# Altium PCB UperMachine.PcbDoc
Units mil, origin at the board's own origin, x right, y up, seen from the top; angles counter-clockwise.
Board outline 2283.46 x 2283.46 mil, 2 copper layers (Top Layer, Bottom Layer); 62 components, 71 nets, 256 pads, 137 vias.
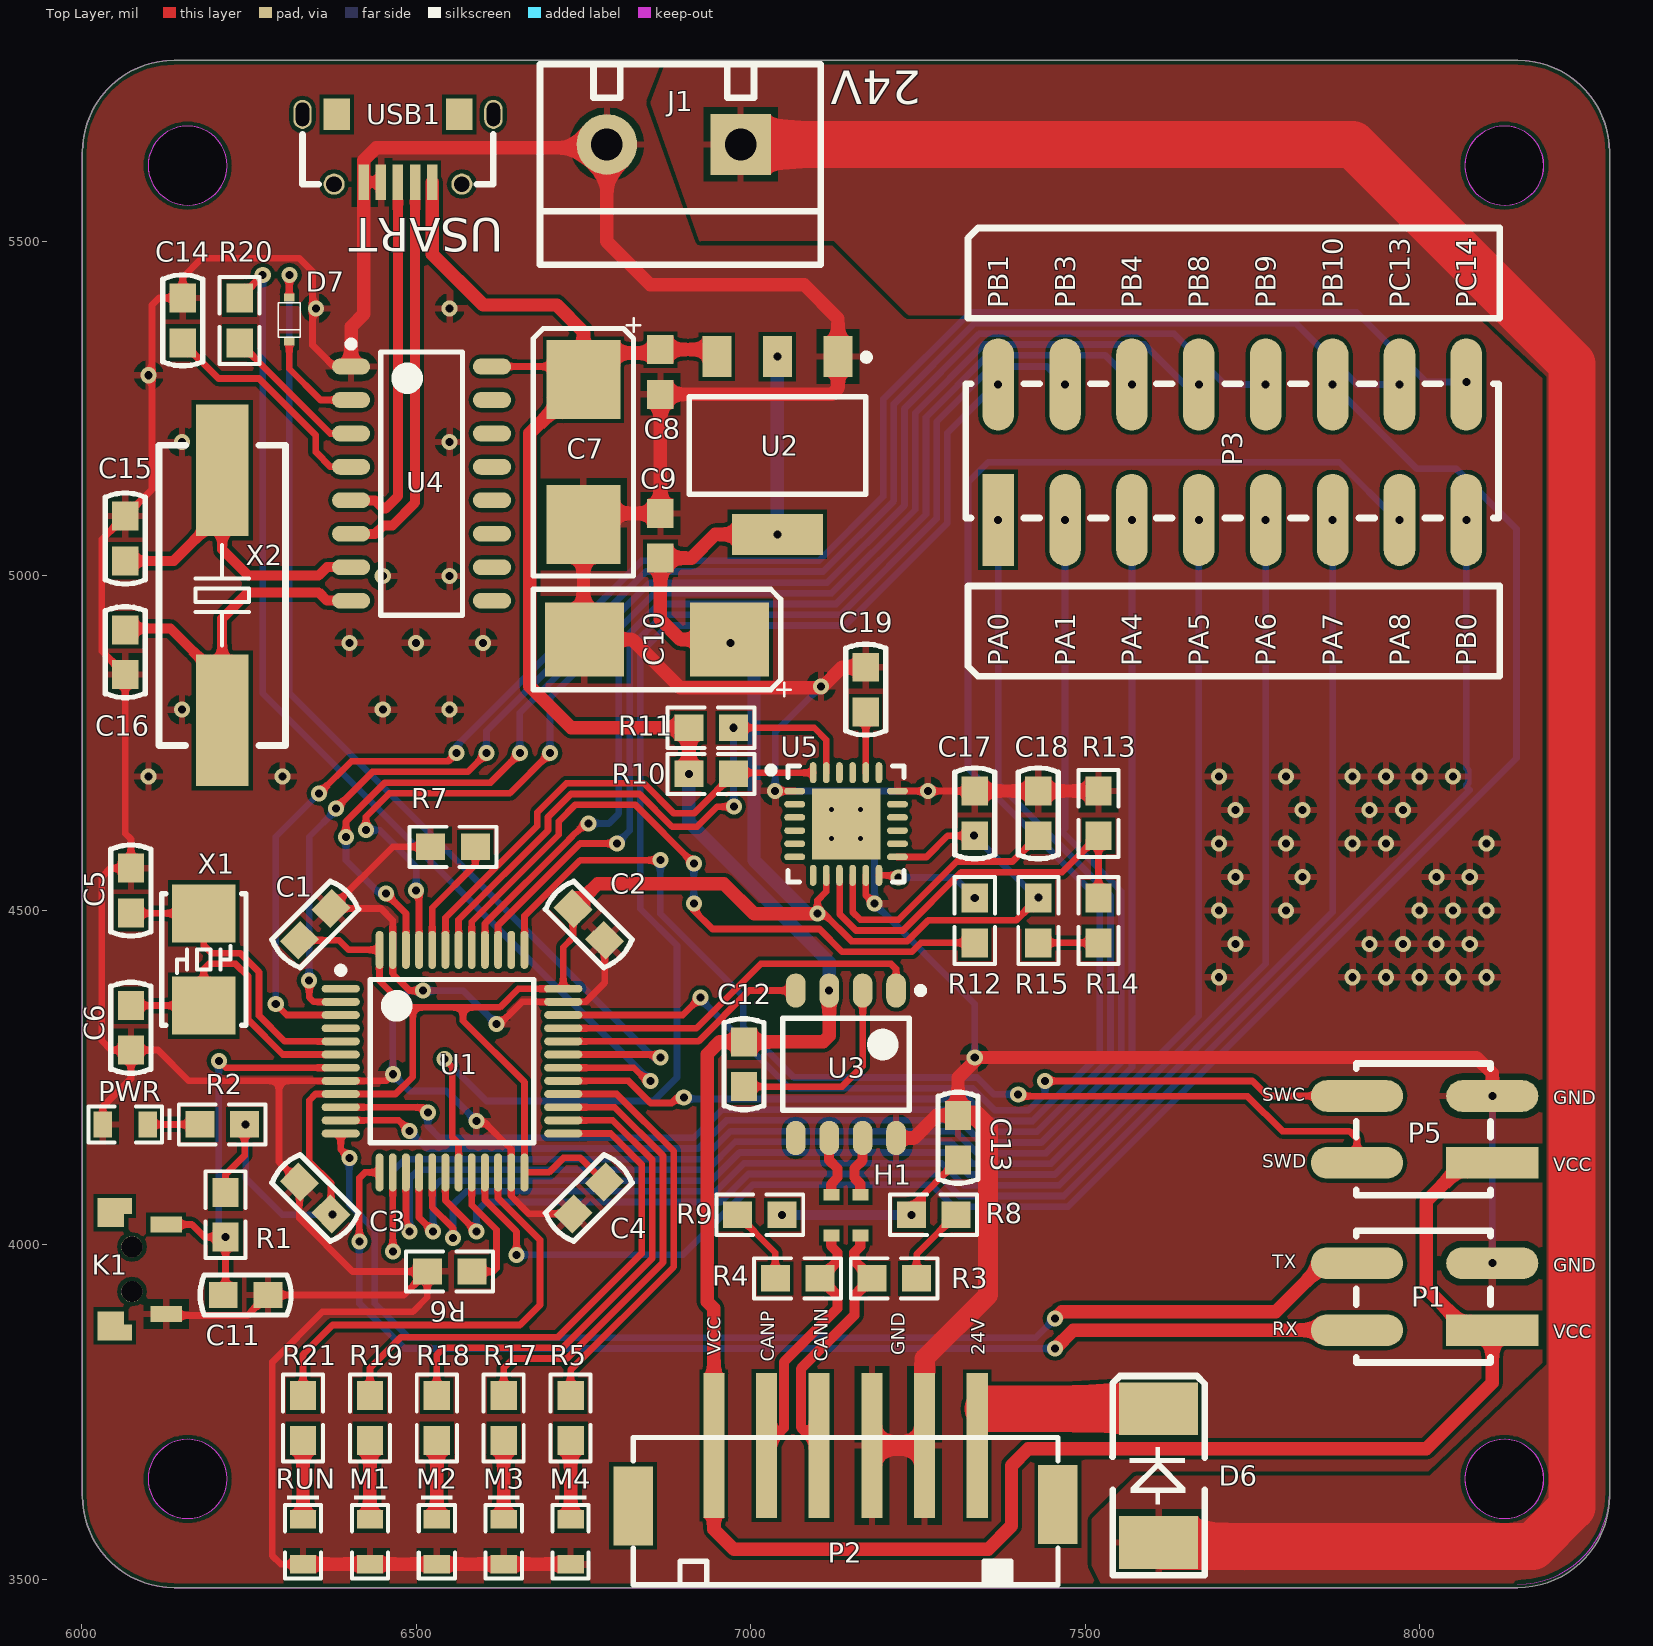
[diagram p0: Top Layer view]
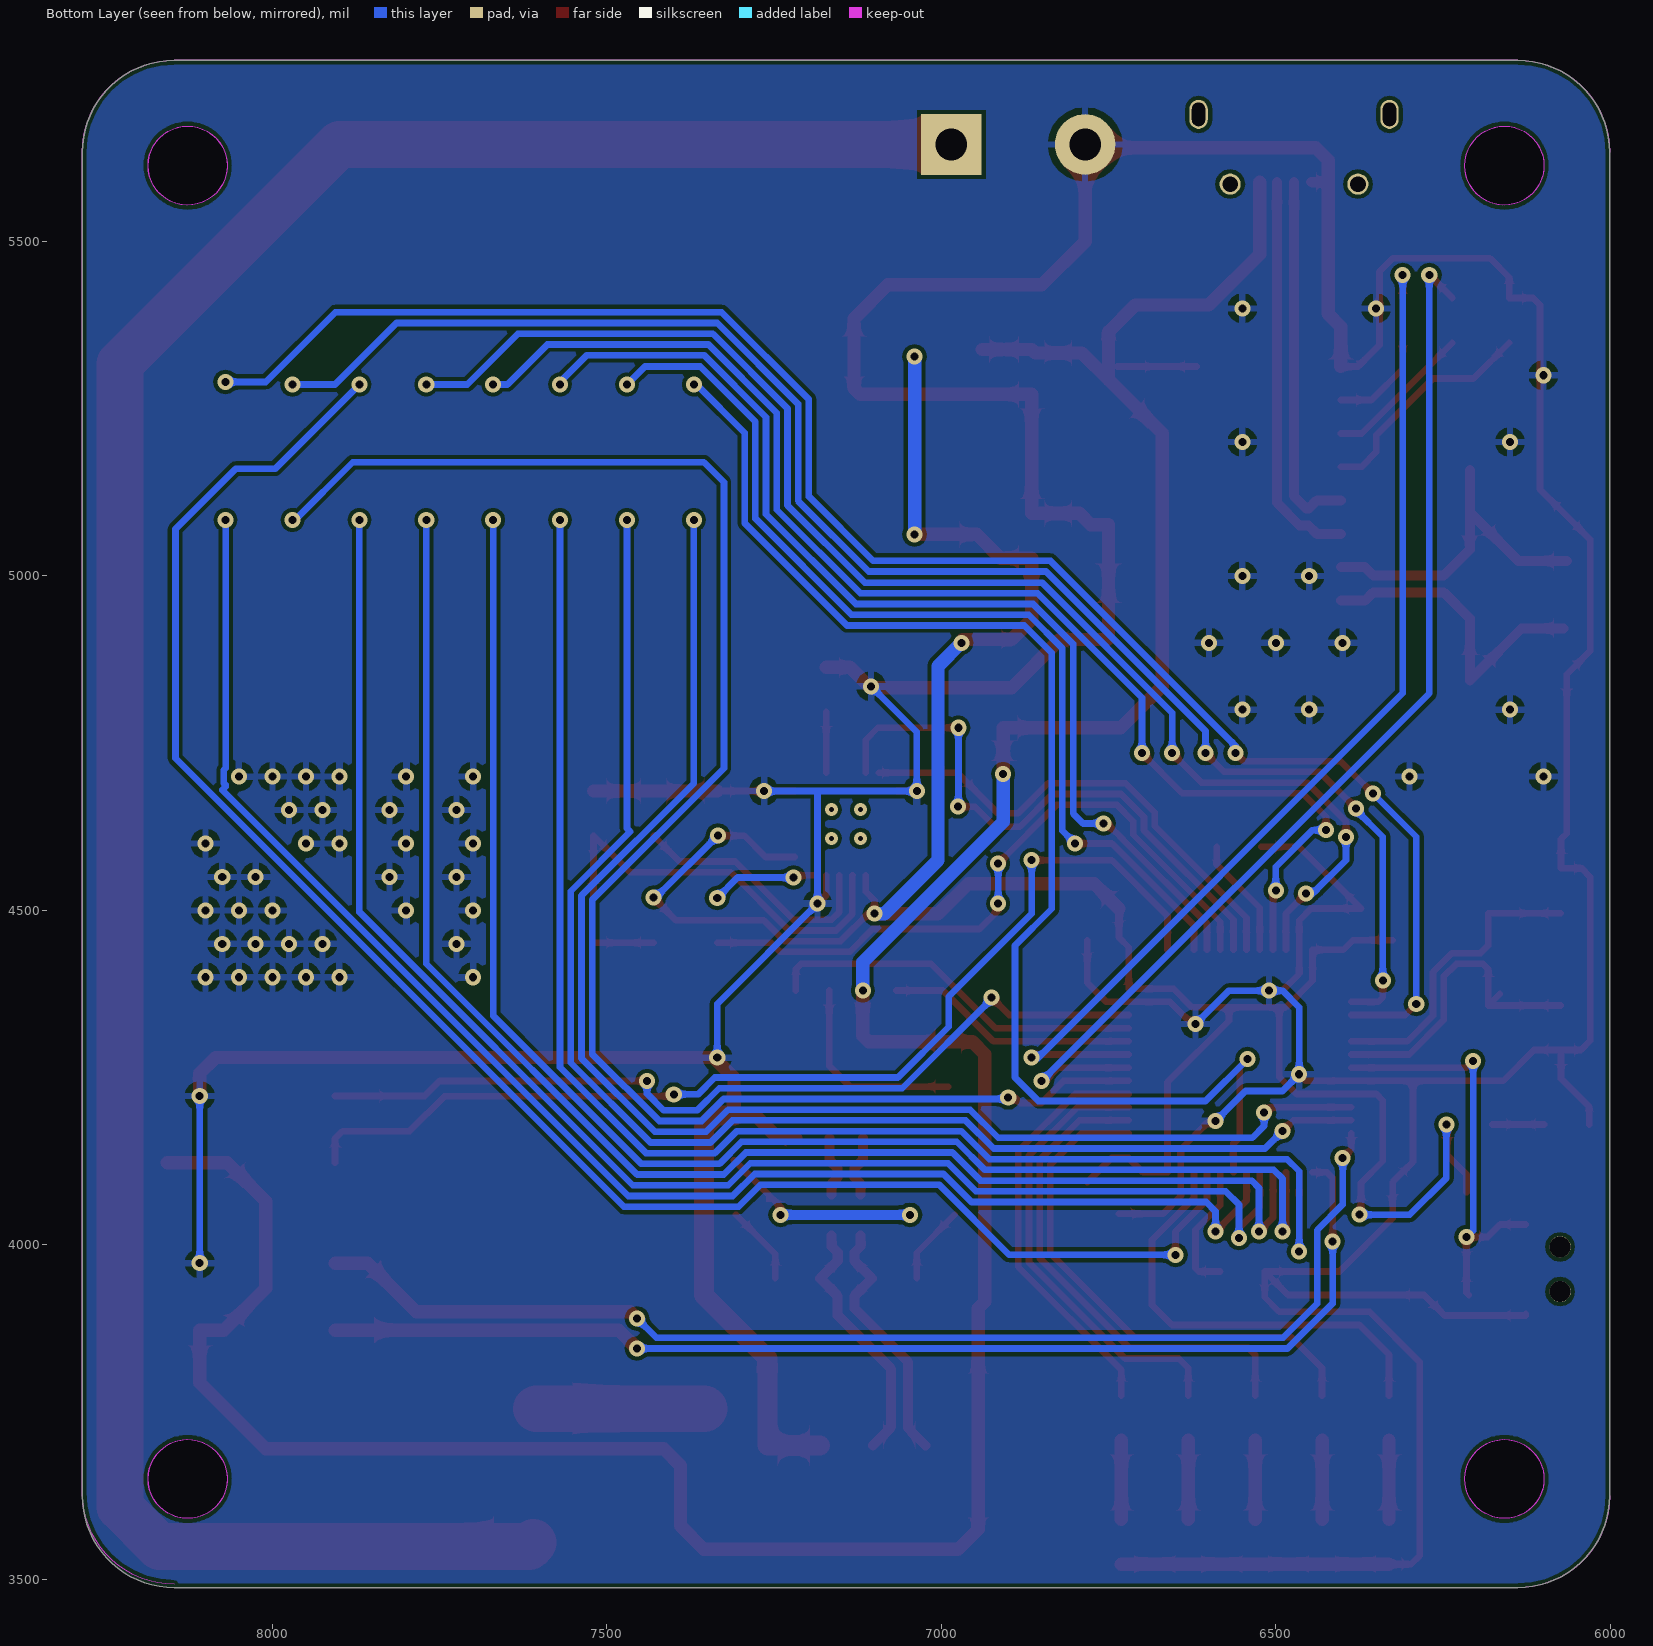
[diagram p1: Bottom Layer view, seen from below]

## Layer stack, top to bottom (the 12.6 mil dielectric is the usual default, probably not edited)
Top Solder: solder mask 0.4, Solder Resist, Dk 3.5
Top Layer: signal copper 1.4
Dielectric 1: dielectric 12.6, FR-4, Dk 4.8
Bottom Layer: signal copper 1.4
Bottom Solder: solder mask 0.4, Solder Resist, Dk 3.5

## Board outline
6000.79,3625.18 ccw(c6138.58,3625.18) 6138.58,3487.38 8146.46,3487.38 ccw(c8146.46,3625.18) 8284.25,3625.18 8284.25,5633.05 ccw(c8146.46,5633.05) 8146.46,5770.85 6138.58,5770.85 ccw(c6138.58,5633.05) 6000.79,5633.05
cut-out: 6099.21,5613.37 ccw(c6158.27,5613.37) 6158.27,5554.31 ccw(c6158.27,5613.37) 6217.32,5613.37 ccw(c6158.27,5613.37) 6158.27,5672.42 ccw(c6158.27,5613.37)
cut-out: 8067.72,5613.37 ccw(c8126.77,5613.37) 8126.77,5554.31 ccw(c8126.77,5613.37) 8185.83,5613.37 ccw(c8126.77,5613.37) 8126.77,5672.42 ccw(c8126.77,5613.37)
cut-out: 6099.21,3649.96 ccw(c6158.27,3649.96) 6158.27,3590.91 ccw(c6158.27,3649.96) 6217.32,3649.96 ccw(c6158.27,3649.96) 6158.27,3709.02 ccw(c6158.27,3649.96)
cut-out: 8067.72,3649.96 ccw(c8126.77,3649.96) 8126.77,3590.91 ccw(c8126.77,3649.96) 8185.83,3649.96 ccw(c8126.77,3649.96) 8126.77,3709.02 ccw(c8126.77,3649.96)

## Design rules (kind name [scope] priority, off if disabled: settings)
Clearance [All] p1: gap=6
DiffPairsRouting [All] p1: maxlimit=10 minlimit=10 mostfreqgap=10 toplayer_minwidth=15 toplayer_maxwidth=15 toplayer_prefwidth=15 bottomlayer_minwidth=15 bottomlayer_maxwidth=15 bottomlayer_prefwidth=15 maxuncoupledlength=500
PolygonConnect [All] p1: connectstyle=Relief reliefconductorwidth=10 reliefentries=4 polygonreliefangle="90 Angle" airgapwidth=10
RoutingVias [All] p1: holewidth=12 width=24 viastyle="Through Hole" minholewidth=6 minwidth=12 maxholewidth=25 maxwidth=50
SolderMaskExpansion [All] p1: expansion=4
Width [All] p1: maxlimit=100 minlimit=6 preferedwidth=10
29 further rules are at their usual default settings.

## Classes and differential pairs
differential pair IN: +IN_P -IN_N
differential pair CAN: +CAN_P -CAN_N
differential pair USB: +USB_P -USB_N
differential pair X: +X_P -X_N

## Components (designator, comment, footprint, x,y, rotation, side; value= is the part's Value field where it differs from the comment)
C1 "104" Cap-0603 6349,4479 r225 top
C2 "104" Cap-0603 6758,4479 r135 top
C3 "104" Cap-0603 6349,4070 r315 top
C4 "104" Cap-0603 6758,4070 r45 top
C5 "22pf" Cap-0603 6073.5,4529.6 r90 top
C6 "22pf" Cap-0603 6073.5,4324.6 r270 top
C7 "100uf" tan_cap_C 6750,5185 r270 top
C8 "104" Cap-0603-M 6865,5305 r90 top
C9 "104" Cap-0603-M 6865,5060 r270 top
C10 "100uf" tan_cap_C 6860,4905 r180 top
C11 "105" Cap-0603 6245,3925 r180 top
C12 "104" Cap-0603 6990,4270 r270 top
C13 "100nf" Cap-0603 7310,4160 r90 top
C14 "0.01uf" Cap-0603 6151,5382 r270 top
C15 "22pf" Cap-0603 6065,5056 r90 top
C16 "22pf" Cap-0603 6065,4886 r270 top
C17 "104" Cap-0603 7335,4645 r270 top
C18 "104" Cap-0603 7430,4645 r270 top
C19 "10uf" Cap-0603 7172,4830 r90 top
D6 "1N5824" DO-214AC/SMA 7610,3560 r90 top
D7 "DIODE" SOD-523 6327,5408 r270 top
H1 "共模扼流圈" 共模扼流圈 7164,4074.9 r270 top
J1 "KF301-2P" KF301-5.0-2P 6985,5645 r180 top
K1 "KEY" SW-SMD-2X4 6075,3930 r90 top
M1 "LED_SMD_WHITE" LED_0603_W 6430.8,3556.04 r270 top (schematic designator D5)
M2 "LED_SMD_WHITE" LED_0603_W 6530.8,3556.04 r270 top (schematic designator D4)
M3 "LED_SMD_WHITE" LED_0603_W 6630.8,3556.04 r270 top (schematic designator D3)
M4 "LED_SMD_WHITE" LED_0603_W 6730.8,3556.04 r270 top (schematic designator D2)
P1 "Header_2X2" Header_SMD_2.54X2 8007.5,3922.5 r90 top
P2 "PH2.0-6P" PH2.0S-6P 7338.7,3699.9 r180 top
P3 "Header_2X8" Header_SMD_2.54X8 7720,5185 r0 top
P5 "Header_2X2" Header_SMD_2.54X2 8007.5,4172.5 r90 top
PWR "LED_BLUE" LED_0603_B 6065,4180 r180 top
R1 "10K" Res-0603 6215,4045 r270 top
R2 "470R" Res-0603 6210,4180 r180 top
R3 "60R" Res-0603 7214.6,3949.9 r0 top
R4 "60R" Res-0603 7070.3,3949.9 r0 top
R5 "470R" Res-0603 6730.8,3741.04 r270 top
R6 "10K" Res-0603 6550,3960 r180 top
R7 "10K" Res-0603 6555,4595 r0 top
R8 "0R" Res-0603 7273.6,4044.9 r180 top
R9 "0R" Res-0603 7013.6,4044.9 r180 top
R10 "4.7K" Res-0603 6941,4704 r180 top
R11 "4.7K" Res-0603 6941,4773 r180 top
R12 "470R" Res-0603 7335,4485 r90 top
R13 "10K" Res-0603 7520,4645 r270 top
R14 "470R" Res-0603 7520,4485 r90 top
R15 "0R" Res-0603 7430,4485 r270 top
R17 "470R" Res-0603 6630.8,3741.04 r270 top
R18 "470R" Res-0603 6530.8,3741.04 r270 top
R19 "470R" Res-0603 6430.8,3741.04 r270 top
R20 "470R" Res-0603 6236,5382 r270 top
R21 "470" Res-0603 6330.8,3741.04 r270 top
RUN "LED_SMD_BLUE" LED_0603_B 6330.8,3556.04 r270 top (schematic designator D8)
U1 "stm32f103c8t6" stm32f103c8t6 6553.5,4274.6 r0 top
U2 "AMS1117" AMS1117 7040,5195 r180 top
U3 "tja1050" tja1050 7142.43,4269.9 r270 top
U4 "CH340G" SOP127P590X265-16N 6508,5138 r0 top
U5 "MPU6050" QFN50P400X400X95_HS-25N 7142.6,4629.1 r0 top
USB1 "USB-MICRO" USB-MICRO-SMD_C 6330,5690 r0 top
X1 "XTAL-2P" "OSC 5032-2P" 6182.5,4426.6 r90 top
X2 "12M" "OSC HC-49SMD" 6210,4971 r270 top

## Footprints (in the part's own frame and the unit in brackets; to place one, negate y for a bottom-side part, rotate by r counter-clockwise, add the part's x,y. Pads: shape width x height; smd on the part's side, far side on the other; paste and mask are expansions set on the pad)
AMS1117 [mm]
  rect 1.1x1.55 smd: 1(-2.3,-3.375) 2(0,-3.375) 3(2.3,-3.375)
  rect 3.45x1.55 smd: 4(0,3.375)
  silkscreen extent -3.5,-3.48 3.35,1.85, body extent -3.25,-3.48 3.25,3.48, height 1.7
Cap-0603 [mm]
  rect 1.1x1 smd: 1(-0.85,0) 2(0.85,0)
  silkscreen extent -1.73,-0.76 1.73,0.76, body extent -0.8,-0.4 0.8,0.4, height 0.6
Cap-0603-M [mm]
  rect 1.1x1 smd: 1(-0.85,0) 2(0.85,0)
  body extent -0.8,-0.4 0.8,0.4, height 0.6
DO-214AC/SMA [mm] "塑封二极管"
  rect 2x3 smd: A(-0.127,0) K(4.953,0)
  silkscreen extent -1.37,-1.75 6.2,1.75, body extent 0.11,-1.35 4.71,1.35, height 2.4
Header_SMD_2.54X2 [mm]
  rect 1.2x3.5 smd: 1(-1.27,-2.57)
  oval 1.2x3.5 smd: 2(1.27,-2.57) 3(1.27,2.57) 4(-1.27,2.57)
  silkscreen extent -2.5,-2.5 2.5,2.6, body extent -2.58,-3.75 2.5,3.75, height 9.7
Header_SMD_2.54X8 [mm]
  rect 1.2x3.5 smd: 1(-8.89,-2.57)
  oval 1.2x3.5 smd: 2(-6.35,-2.57) 3(-3.81,-2.57) 4(-1.27,-2.57) 5(1.27,-2.57) 6(3.81,-2.57) 7(6.35,-2.57) 8(8.89,-2.57) 9(8.89,2.57) 10(6.35,2.57) 11(3.81,2.57) 12(1.27,2.57) 13(-1.27,2.57) 14(-3.81,2.57) 15(-6.35,2.57) 16(-8.89,2.57)
  silkscreen extent -10.12,-2.5 10.11,2.6, body extent -10.2,-3.75 10.12,3.75, height 9.7
KF301-5.0-2P [mm] "可拼接端子/6A"
  rect 2.3x2.3 hole 1.2: 1(0,0)
  round 2.3 hole 1.2: 2(5.08,0)
  silkscreen extent -3.05,-3.05 7.62,4.57, body extent -3,-3.09 7.5,4.51, height 10.05
LED_0603_B [mm]
  rect 0.7x1 smd: 1(-0.85,0) 2(0.85,0)
  silkscreen extent -1.75,-0.69 1.4,0.69, body extent -0.8,-0.42 0.8,0.38, height 0.61
LED_0603_W [mm]
  rect 0.7x1 smd: 1(-0.85,0) 2(0.85,0)
  silkscreen extent -1.75,-0.69 1.4,0.69, body extent -0.8,-0.42 0.8,0.38, height 0.61
"OSC 5032-2P" [mm]
  rect 2.2x2.4 smd: 1(-1.75,0) 2(1.75,0)
  silkscreen extent -2.5,-1.6 2.5,1.6, body extent -2.5,-1.52 2.5,1.68, height 0.86
"OSC HC-49SMD" [mm]
  rect 5x2 smd: 1(-4.75,0) 2(4.75,0)
  silkscreen extent -5.7,-2.4 5.7,2.4, body extent -6.37,-2.41 6.63,2.24, height 4.63
PH2.0S-6P [mm]
  rect 1.5x3 smd: 0(-3.064,2.238) 0(13.064,2.286)
  rect 0.8x5.5 smd: 1(0,0) 2(2,0) 3(4,0) 4(6,0) 5(8,0) 6(10,0)
  silkscreen extent -3.06,-0.3 13.06,5.29, body extent -3,-2.5 13,5.3, height 6.15
QFN50P400X400X95_HS-25N [mm] "QFN, 24-Leads, Body 4.00x4.00mm, Pitch 0.50mm, Thermal Pad 2.60x2.70mm, IPC Medium Density"
  oval 0.8x0.25 smd: 1(-1.95,1.25) 2(-1.95,0.75) 3(-1.95,0.25) 4(-1.95,-0.25) 5(-1.95,-0.75) 6(-1.95,-1.25) 13(1.95,-1.25) 14(1.95,-0.75) 15(1.95,-0.25) 16(1.95,0.25) 17(1.95,0.75) 18(1.95,1.25)
  oval 0.25x0.8 smd: 7(-1.25,-1.95) 8(-0.75,-1.95) 9(-0.25,-1.95) 10(0.25,-1.95) 11(0.75,-1.95) 12(1.25,-1.95) 19(1.25,1.95) 20(0.75,1.95) 21(0.25,1.95) 22(-0.25,1.95) 23(-0.75,1.95) 24(-1.25,1.95)
  rect 2.6x2.7 smd: 25(0,0)
  silkscreen extent -2.97,-2.2 2.2,2.2, body extent -2.05,-2.05 2.05,2.05, height 0.95
Res-0603 [mm]
  rect 1.1x1 smd: 1(-0.85,0) 2(0.85,0)
  silkscreen extent -1.65,-0.76 1.65,0.76, body extent -0.8,-0.4 0.8,0.4, height 0.38
SOD-523 [mm] "塑封二极管"
  rect 0.3x0.4 smd: A(-0.203,-0.425) K(1.473,-0.425)
  silkscreen extent 0,-0.85 1.3,0, body extent -0.16,-0.83 1.44,-0.03, height 0.65
SOP127P590X265-16N [mm] "SOP, 16-Leads, Body 9.90x3.90mm, Pitch 1.27mm, IPC Medium Density"
  oval 1.45x0.6 smd: 1(-2.675,4.445) 2(-2.675,3.175) 3(-2.675,1.905) 4(-2.675,0.635) 5(-2.675,-0.635) 6(-2.675,-1.905) 7(-2.675,-3.175) 8(-2.675,-4.445) 9(2.675,-4.445) 10(2.675,-3.175) 11(2.675,-1.905) 12(2.675,-0.635) 13(2.675,0.635) 14(2.675,1.905) 15(2.675,3.175) 16(2.675,4.445)
  silkscreen extent -2.8,-5 1.55,5.42, body extent -1.95,-5 1.95,5, height 2.65
stm32f103c8t6 [mm] "QFP, 100-Leads, Body 14.00x20.00mm, Pitch 0.65mm, IPC Medium Density"
  oval 1.45x0.3 smd: 1(-4.225,2.75) 2(-4.225,2.25) 3(-4.225,1.75) 4(-4.225,1.25) 5(-4.225,0.75) 6(-4.225,0.25) 7(-4.225,-0.25) 8(-4.225,-0.75) 9(-4.225,-1.25) 10(-4.225,-1.75) 11(-4.225,-2.25) 12(-4.225,-2.75) 25(4.225,-2.75) 26(4.225,-2.25) 27(4.225,-1.75) 28(4.225,-1.25) 29(4.225,-0.75) 30(4.225,-0.25) 31(4.225,0.25) 32(4.225,0.75) 33(4.225,1.25) 34(4.225,1.75) 35(4.225,2.25) 36(4.225,2.75)
  oval 0.3x1.45 smd: 13(-2.75,-4.225) 14(-2.25,-4.225) 15(-1.75,-4.225) 16(-1.25,-4.225) 17(-0.75,-4.225) 18(-0.25,-4.225) 19(0.25,-4.225) 20(0.75,-4.225) 21(1.25,-4.225) 22(1.75,-4.225) 23(2.25,-4.225) 24(2.75,-4.225) 37(2.75,4.225) 38(2.25,4.225) 39(1.75,4.225) 40(1.25,4.225) 41(0.75,4.225) 42(0.25,4.225) 43(-0.25,4.225) 44(-0.75,4.225) 45(-1.25,4.225) 46(-1.75,4.225) 47(-2.25,4.225) 48(-2.75,4.225)
  silkscreen extent -4.35,-3.1 3.1,3.57, body extent -3.5,-3.5 3.5,3.5, height 1.6
SW-SMD-2X4 [mm]
  rect 0.6x1.3 smd: 0(-1.55,0.65) 0(3.25,0.65)
  rect 0.6x1 smd: 0(-1.05,0.8) 0(2.75,0.8)
  round 0.8 hole 0.8: 0(0,0) 0(1.7,0)
  rect 0.6x1.2 smd: 1(-0.85,-1.3) 3(2.55,-1.3)
  body extent -2.97,-1.8 4.83,1.8, height 3.5
tan_cap_C [mm]
  rect 3x2.8 smd: 1(-2.75,0) 2(2.75,0)
  silkscreen extent -5.08,-1.91 4.7,2.16, body extent -3.15,-1.6 3.15,1.6, height 2.5
tja1050 [mm] "SOP, 8-Leads, Body 4.90x3.90mm, Pitch 1.27mm, IPC Medium Density"
  oval 1.3x0.75 smd: 1(-2.8,1.905) 2(-2.8,0.635) 3(-2.8,-0.635) 4(-2.8,-1.905) 5(2.8,-1.905) 6(2.8,-0.635) 7(2.8,0.635) 8(2.8,1.905)
  silkscreen extent -2.92,-2.4 1.75,2.96, body extent -1.9,-2.4 1.9,2.4, height 1.75
USB-MICRO-SMD_C [mm]
  oval 0.7x1.1 hole 0.5 slot 0.9 at 90 deg: 0(0,0) 0(7.25,0)
  round 0.8 hole 0.6: 0(1.2,-2.65) 0(6.05,-2.65)
  rect 1x1.2 smd: 0(1.3,0) 0(5.95,0)
  rect 0.4x1.35 smd: 1(4.925,-2.575) 2(4.275,-2.575) 3(3.625,-2.575) 4(2.975,-2.575) 5(2.325,-2.575)
  silkscreen extent 0,-2.65 7.24,-0.76, body extent -0.37,-2.87 7.63,2.73, height 2.8
共模扼流圈 [mm]
  rect 0.45x0.6 smd: 1(0,0) 2(0,-1.1) 3(1.55,-1.1) 4(1.55,0)

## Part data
C1 C2 C3 C4 C5 C6 C8 C9 C11 C12 C13 C15 C16 C17 C18 C19: library part CAP
C7 C10: library part tan_cap
C14: library part Cap
D6: library part DIODE, "普通二极管"
D7: "普通二极管"
M1 M2 M3 M4 RUN: "发光二极管"
PWR: library part LED_SMD_BLUE, "发光二极管"
R1 R2 R3 R4 R5 R6 R7 R8 R9 R10 R11 R12 R13 R14 R15 R17 R18 R19 R20 R21: library part RES, "贴片电阻"
X1: "2脚无源脚晶振"
X2: library part XTAL-2P, "2脚无源脚晶振"

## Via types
v1: diameter 24, hole 12, Top Layer to Bottom Layer, 133 vias
v2: diameter 19.68, hole 7.87, Top Layer to Bottom Layer, 4 vias

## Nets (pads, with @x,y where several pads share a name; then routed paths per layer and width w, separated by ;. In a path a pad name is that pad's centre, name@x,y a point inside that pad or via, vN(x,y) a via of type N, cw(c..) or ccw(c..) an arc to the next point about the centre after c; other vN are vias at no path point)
3.3V: C1.2 C2.2 C3.2 C4.2 C9.2 C10.1 C17.2 R1.1 R2.1 R15.1 U1.9 U1.24 U1.36 U1.48 U2.2 U2.4 U5.8 U5.13 | length 4061.6
  Top Layer w10: R1.1 6215,4105 6243.46,4133.46 R2.1 ; C1.2 6384.66,4455.34 6399.06,4440.94 U1.48 6445.23,4394.77 6485,4355 6625,4355 6652.87,4382.87 U1.36 6719.84,4444.84 6734.34,4459.34 C2.2 ; C3.2 6372.66,4092.34 6340,4125 6340,4216 6349.39,4225.39 U1.9 6469.09,4225.39 6495,4251.3 6495,4355 ; 6570,4355 6570,4335 6661.77,4243.23 U1.24 6698.26,4108.26 6720,4130 6745.33,4130 C4.2 ; U5.8 7113.07,4528.07 7100,4515 v1(7100,4495) 7109.75,4495 7150.75,4454 7234.25,4454 7265.25,4485 7396.54,4485 R15.1 ; U5.13 7262.89,4579.89 7294.54,4611.54 C17.2
  Top Layer w20: C2.2 6771.67,4540 6960,4540 7005,4495 v1(7100,4495) ; C10.1 6895,4905 6865,4935 C9.2 6911.54,5026.54 6947.13,5062.13 v1(7040,5062.13)
  Bottom Layer w10: v1(6245,4180) 6245,4100 6300,4045 v1(6375,4045) ; v1(7334,4612) 7427,4519 v1(7430,4519)
  Bottom Layer w20: v1(6970,4900) 7005,4865 7005,4575 7085,4495 v1(7100,4495) ; v1(7040,5062.13) v1(7040,5327.87)
24V: D6.A J1.1 | length 3732.8
  Top Layer w70: J1.1 7900,5645 8227.94,5317.06 8227.94,3608.06 8168.68,3548.79 7616.21,3548.79 D6.A
AD0: R13.2 R14.2 U5.9 | length 606.8
  Top Layer w10: U5.9 7133,4552.09 7133,4494.37 7157.37,4470 7227.63,4470 7314.63,4557 7465.46,4557 R13.2 R14.2
BOOT0: R7.2 U1.44 | length 180.8
  Top Layer w10: U1.44 6523.97,4503.97 6588.46,4568.46 R7.2
BOOT1: R6.1 U1.20 | length 197.2
  Top Layer w10: U1.20 6583.03,4059.5 6620,4022.53 6620,3965 6615,3960 R6.1
CAN_N: H1.4 P2.4 R3.1 | length 384
  Top Layer w15: P2.4 7075,3727.38 7075,3814.69 7154.95,3894.64 7154.95,3923.71 R3.1 7154.85,3976.19 7154.85,3988.36 7164,3997.52 H1.4
CAN_P: H1.3 P2.5 R4.2 | length 383.4
  Top Layer w15: P2.5 7050,3726.16 7050,3825.05 7129.95,3905 7129.95,3923.71 R4.2 7129.85,3975.98 7129.85,3988.36 7120.69,3997.52 H1.3
CAN_RX: U1.32 U3.4 | length 379.1
  Top Layer w10: U1.32 6921.76,4304.13 6997.76,4380.14 U3.4
CAN_TX: U1.33 U3.1 | length 572.9
  Top Layer w10: U1.33 6918.81,4323.81 7015,4420 7210,4420 7217.43,4412.57 U3.1
GND: C1.1 C2.1 C3.1 C4.1 C5.2 C6.2 C7.2 C8.1 C9.1 C10.2 C11.1 C13.2 C14.1 C15.2 C16.2 C17.1 C18.1 C19.2 J1.2 K1.1 M1.2 M2.2 M3.2 M4.2 P1.2 P2.2 P2.3 P5.2 PWR.2 R6.2 R7.1 R13.1 RUN.2 U1.8 U1.23 U1.35 U1.47 U2.1 U3.8 U4.1 U5.1 U5.11 U5.18 USB1.4 USB1.5 | length 11248.8
  Top Layer w10: PWR.2 6031.53,4206.53 6073.5,4248.5 C6.2 ; K1.1 6126.18,3894.31 6247.78,3894.31 C11.1 6481.54,3925 R6.2 ; RUN.2 6297.44,3522.56 6285,3535 6285,3825 6360,3900 6495,3900 6516.54,3921.54 R6.2 ; U4.1 6377,5313 6345,5345 6345,5455 6325,5475 6180,5475 6151,5446 C14.1 6115.46,5415.46 6105,5405 6105,5129.46 C15.2 6030,5054.46 6030,4887.54 C16.2 6065,4615 6073.5,4606.5 C5.2 6043.06,4563.06 6030,4550 6030,4305 6043.86,4291.14 C6.2 ; v1(6465,4255) 6455.07,4245.07 U1.8 6295,4245.07 ; v1(6510,4380) 6490,4380 6464.92,4405.08 U1.47 6464.92,4485.08 6447.34,4502.66 C1.1 6465,4595 R7.1 ; v1(6590,4185) 6600,4185 6642.08,4142.92 U1.23 6642.08,4072.92 6668.66,4046.34 C4.1 ; v1(6620,4330) 6625,4330 6658.18,4363.18 U1.35 6753.18,4363.18 6781.66,4391.66 C2.1 ; v1(7036.69,4678.31) U5.1 ; U5.11 7172.13,4522.87 v1(7185,4510) ; U5.18 v1(7265,4678.31) C17.1@7334.85,4678.31 ; C6.2 6113.86,4291.14 6159.93,4245.07 6295,4245.07 ; 6295,4245.07 6295,4124 C3.1 6325.34,4039.66 6405,3960 R6.2
  Top Layer w15: USB1.5 USB1.4
  Top Layer w20: RUN.2 M1.2 M2.2 M3.2 M4.2 ; U4.1 6402.69,5372.69 6421.54,5391.54 USB1.5 6421.54,5621.54 6440,5640 6780,5640 J1.2 6785,5500 6850,5435 7080,5435 7130.55,5384.45 U2.1 7130.55,5280.55 7121.54,5271.54 C8.1 C9.1 6793.46,5093.46 6776.73,5076.73 C7.2 6750,4906.73 C10.2 6823,4905 6895,4833 7106,4833 7136.46,4863.46 C19.2 ; U3.8 7244.66,4159.66 7278.46,4193.46 C13.2 7310,4250 7340,4280 8085,4280 8108.68,4256.32 v1(8108.68,4222.5) ; C17.1 C18.1 R13.1
  Top Layer w30: P2.3 P2.2 7259.96,3829.96 7355,3925 7355,4175 7336.54,4193.46 C13.2
  Bottom Layer w10: v1(6590,4185) 6545,4230 6490,4230 v1(6465,4255) 6465,4355 6490,4380 v1(6510,4380) 6570,4380 v1(6620,4330) ; v1(7105,4835) 7036.69,4766.69 v1(7036.69,4678.31) 7185,4678.31 ; v1(7185,4510) 7335,4360 v1(7335,4280) ; v1@7185.1,4510.1 7185.1,4678.22 7185,4678.31 ; v1(7265,4678.31) 7185,4678.31 ; v1(8108.68,3972.5) v1(8108.68,4222.5)
  other v1: 7700,4400 7900,4400 7950,4400 8000,4400 8050,4400 8100,4400 7725,4450 7925,4450 7975,4450 8025,4450 8075,4450 7700,4500 7800,4500 8000,4500 8050,4500 8100,4500 7725,4550 7825,4550 8025,4550 8075,4550 7700,4600 7800,4600 7900,4600 7950,4600 8100,4600 7725,4650 7825,4650 7925,4650 7975,4650 6100,4700 6300,4700 7700,4700 7800,4700 7900,4700 7950,4700 8000,4700 8050,4700 6150,4800 6450,4800 6550,4800 6400,4900 6500,4900 6600,4900 6450,5000 6550,5000 6150,5200 6550,5200 6100,5300 6350,5400 6550,5400
IN_N: H1.1 U3.7 | length 93.7
  Top Layer w15: H1.1 7164,4091.26 7154.93,4100.33 7154.93,4114.07 7167.43,4126.57 U3.7
IN_P: H1.2 U3.6 | length 93.8
  Top Layer w15: U3.6 7117.43,4126.57 7129.93,4114.07 7129.93,4100.5 7120.69,4091.26 H1.2
JTCK: P5.4 U1.37 | length 1611.7
  Top Layer w10: U1.37 6661.77,4491.77 6745,4575 v1(6865,4575) ; v1(7400,4225) 7403,4222 7743,4222 7795,4170 7895,4170 7906.32,4158.68 P5.4
  Bottom Layer w10: v1(6865,4575) 6865,4495 6989,4371 6989,4326 7065,4250 7338.65,4250 7363.65,4225 v1(7400,4225)
JTMS: P5.3 U1.34 | length 1307.7
  Top Layer w10: U1.34 6898.5,4343.5 v1(6925,4370) ; v1(7440,4245) 7750,4245 7772.5,4222.5 P5.3
  Bottom Layer w10: v1(6925,4370) 6925,4367.37 7058.37,4234 7332.02,4234 7365.02,4201 7414.98,4201 7440,4226.02 v1(7440,4245)
NetC12_2: C12.2 U3.2 | length 302.9
  Top Layer w10: C12.2 7136.54,4236.54 7167.43,4267.43 U3.2
NetC13_1: C13.1 R8.2 R9.1 | length 303.6
  Top Layer w10: v1(7240.14,4044.9) 7240.14,4056.67 C13.1
  Bottom Layer w15: v1(7047.06,4044.9) v1(7240.14,4044.9)
NetC14_2: C14.2 U4.4 | length 343.2
  Top Layer w10: C14.2 6204.54,5295 6265,5295 6350,5210 6350,5185 6372,5163 U4.4
NetC18_2: C18.2 U5.10 | length 389.1
  Top Layer w10: U5.10 7152.44,4497.56 7164,4486 7221,4486 7308,4573 7391.46,4573 C18.2
NetC19_1: C19.1 U5.20 | length 90.7
  Top Layer w10: C19.1 7172.13,4796.41 U5.20
NetD6_K: D6.K P2.1 | length 250
  Top Layer w70: 7355,3755 D6.K@7605,3755
NetD7_K: D7.K U4.2 | length 152
  Top Layer w10: D7.K 6310.27,5309.73 6357,5263 U4.2
NetM1_1: M1.1 R19.2 | length 118.1
  Top Layer w20: M1.1 R19.2
NetM2_1: M2.1 R18.2 | length 118.1
  Top Layer w20: M2.1 R18.2
NetM3_1: M3.1 R17.2 | length 118.1
  Top Layer w20: M3.1 R17.2
NetM4_1: M4.1 R5.2 | length 118.1
  Top Layer w20: M4.1 R5.2
NetPWR_1: PWR.1 R2.2 | length 78.1
  Top Layer w10: PWR.1 R2.2
NetR3_2: R3.2 R8.1 | length 119.4
  Top Layer w10: R3.2 7248.06,3985.9 R8.1
NetR4_1: R4.1 R9.2 | length 118.5
  Top Layer w10: R9.2 7036.84,3988.2 R4.1
NetR12_2: R12.2 U5.12 | length 157.2
  Top Layer w10: U5.12 7217.67,4552.33 v1(7221,4549)
  Bottom Layer w10: v1(7221,4549) 7304.46,4549 v1(7335,4518.46)
NetR14_1: R14.1 R15.2 | length 90
  Top Layer w10: R15.2 R14.1
NetR20_2: R20.2 U4.3 | length 222.8
  Top Layer w10: R20.2 6371.54,5213 U4.3
NetR21_2: R21.2 RUN.1 | length 118.1
  Top Layer w20: RUN.1 R21.2
NRST: C11.2 K1.3 R1.2 U1.7 | length 638.6
  Top Layer w10: K1.3 6164.61,4030.39 6183.46,4011.54 v1(6215,4011.54) 6215,3928.46 C11.2 ; v1(6205,4275) 6215.24,4264.76 U1.7
  Bottom Layer w10: v1(6205,4275) 6205,4021.54 v1(6215,4011.54)
OSC8M_IN: C5.1 U1.5 X1.2 | length 458.5
  Top Layer w10: C5.1@6074.14,4495.5 X1.2 6182.5,4447.5 6194,4436 6236.63,4436 6265,4407.63 6265,4342.63 6303.5,4304.13 U1.5
OSC8M_OUT: C6.1 U1.6 X1.1 | length 490
  Top Layer w10: C6.1@6073.86,4357.7 X1.1 ; X1.1@6165.1,4375.1 X1.1 ; U1.6 6300.56,4284.44 6249,4336 6249,4401 6230,4420 6190,4420 6182.5,4412.5 X1.1
PA0: P3.1 U1.10 | length 2132.7
  Top Layer w10: U1.10 6509.3,4205.7 v1(6517.5,4197.5)
  Bottom Layer w10: v1(6517.5,4197.5) 6517.5,4177.5 6535,4160 6915,4160 6957,4202 7318.76,4202 7351.76,4169 7428.24,4169 7538,4278.76 7538,4522 7370,4690 v1(7370,5083.82)
PA1: P3.2 U1.11 | length 2115.3
  Top Layer w10: U1.11 6473.98,4186.02 v1(6490,4170)
  Bottom Layer w10: v1(6490,4170) 6516,4144 6921.63,4144 6963.63,4186 7312.14,4186 7345.14,4153 7434.86,4153 7554,4272.14 7554,4528.63 7465,4617.63 7470,4622.63 v1(7470,5083.82)
PA2: P1.3 U1.12 | length 1811
  Top Layer w10: U1.12 6387.16,4142.84 v1(6400,4130)
  Top Layer w20: v1(7455,3890) 7465,3900 7785,3900 7857.5,3972.5 P1.3
  Bottom Layer w10: v1(6400,4130) 6400,4060 6438,4022 6438,3912 6489,3861 7426,3861 v1(7455,3890)
PA3: P1.4 U1.13 | length 1751.9
  Top Layer w10: v1(6415,4005) 6415,4100 6423.26,4108.26 U1.13
  Top Layer w20: v1(7455,3845) 7482.5,3872.5 P1.4
  Bottom Layer w10: v1(6415,4005) 6415,3912.37 6482.37,3845 v1(7455,3845)
PA4: P3.3 U1.14 | length 2253.4
  Top Layer w10: U1.14 6465,4108.18 v1(6465,3990)
  Bottom Layer w10: v1(6465,3990) 6465,4110 6483,4128 6928.25,4128 6970.25,4170 7305.51,4170 7338.51,4137 7441.49,4137 7570,4265.51 v1(7570,5083.82)
PA5: P3.4 U1.15 | length 2218.8
  Top Layer w10: U1.15 6484.6,4025.4 v1(6490,4020)
  Bottom Layer w10: v1(6490,4020) 6490,4099 6503,4112 6934.88,4112 6976.88,4154 7298.88,4154 7331.88,4121 7448.12,4121 7670,4342.88 v1(7670,5083.82)
PA6: P3.5 U1.16 | length 2236.6
  Top Layer w10: U1.16 6504.29,4040.71 v1(6525,4020)
  Bottom Layer w10: v1(6525,4020) 6525,4085 6536,4096 6941.51,4096 6983.51,4138 7292.25,4138 7325.25,4105 7454.75,4105 7770,4420.25 v1(7770,5083.82)
PA7: P3.6 U1.17 | length 2270.9
  Top Layer w10: U1.17 6523.97,4056.03 6555,4025 v1(6555,4010)
  Bottom Layer w10: v1(6555,4010) 6555,4060 6575,4080 6948.14,4080 6990.14,4122 7285.63,4122 7318.63,4089 7461.37,4089 7870,4497.63 v1(7870,5083.82)
PA8: P3.7 U1.29 | length 2504.6
  Top Layer w10: U1.29 6817.4,4245.07 6850.47,4212 6882,4212 6890,4220 v1(6900,4220)
  Bottom Layer w10: v1(6900,4220) 6902,4218 7325.39,4218 7358.39,4185 7421.61,4185 7522,4285.39 7522,4515.37 7325,4712.37 7325,5140 7355,5170 7880,5170 7966.18,5083.82 v1(7970,5083.82)
PA15: U1.38
PB0: P3.8 U1.18 | length 2319.1
  Top Layer w10: U1.18 6543.66,4066.34 v1(6590,4020)
  Bottom Layer w10: v1(6590,4020) 6590,4050 6604,4064 6954.76,4064 6996.76,4106 7279,4106 7312,4073 7468,4073 8075,4680 8070,4685 8070,4687.47 8073,4690.47 8073,4709.53 8070,4712.53 v1(8070,5083.82)
PB1: P3.16 U1.19 | length 2003.8
  Top Layer w10: v1(6542.5,4277.5) 6553.72,4266.28 6553.72,4161.28 6563.34,4151.66 U1.19
  Bottom Layer w10: v1(6542.5,4277.5) 6605,4215 6855,4215 6890,4250 6890,4447.37 6835,4502.37 6835,4885 6876,4926 7141,4926 7294,5079 7294,5214 7366.18,5286.18 v1(7370,5286.18)
PB3: P3.15 U1.39 | length 1486.2
  Top Layer w10: U1.39 6622.4,4477.14 6745.13,4599.87 6745,4600 v1(6800,4600)
  Bottom Layer w10: v1(6800,4600) 6819,4619 6819,4891.63 6869.37,4942 7134.37,4942 7278,5085.63 7278,5230.53 7360.47,5313 7443,5313 7470,5286 v1(7470,5286.18)
PB4: P3.14 U1.40 | length 1614.2
  Top Layer w10: U1.40 6602.71,4480.09 6729,4606.37 6729,4606.63 6738.37,4616 6738.63,4616 6755,4632.37 v1(6757.37,4630)
  Bottom Layer w10: v1(6757.37,4630) 6788,4630 6803,4645 6803,4898.25 6862.75,4958 7127.75,4958 7262,5092.25 7262,5237.15 7354.85,5330 7530,5330 7570,5290 v1(7570,5286.18)
PB5: R12.1 U1.41 | length 1016
  Top Layer w10: U1.41 6583.03,4483.03 6713,4613 6713,4633 6738,4658 6827,4658 v1(6915,4570) ; v1(6915,4510) 6915,4500 6943,4472 7103,4472 7137,4438 7240.88,4438 7254.42,4451.54 R12.1
  Bottom Layer w10: v1(6915,4510) v1(6915,4570)
PB6: R11.1 U1.42 U5.23 | length 891.6
  Top Layer w10: U1.42 6563.34,4485.97 6697,4619.63 6697,4639.63 6731.37,4674 6833.63,4674 6882.63,4625 6920,4625 6950,4655 v1(6975,4655) ; v1(6974.46,4773) 7095,4773 7113.07,4754.93 U5.23
  Bottom Layer w10: v1@6974.46,4655.54 v1(6974.46,4773)
PB7: R10.1 U1.43 U5.24 | length 733.9
  Top Layer w10: U1.43 6543.66,4488.91 6681,4626.25 6681,4646.25 6724.75,4690 6840.25,4690 6885.25,4645 6915.46,4645 R10.1 ; R10.1@6976.34,4705.87 U5.24
PB8: P3.13 U1.45 | length 1939.3
  Top Layer w10: v1(6425,4620) 6425,4640 6460,4675 6640,4675 v1(6700,4735) ; v1(6500,4530) 6504.29,4525.71 U1.45
  Bottom Layer w10: v1(6425,4620) 6445,4620 6500,4565 v1(6500,4530) ; v1(6700,4735) 6700,4817.88 6856.12,4974 7121.12,4974 7246,5098.88 7246,5243.78 7348.22,5346 7589,5346 7648.82,5286.18 v1(7670,5286.18)
PB9: P3.12 U1.46 | length 2063.5
  Top Layer w10: v1(6395,4610) 6395,4632.63 6453.37,4691 6611,4691 v1(6655,4735) ; v1(6455,4525) 6484.6,4495.4 U1.46
  Bottom Layer w10: v1(6395,4610) 6395,4575 6445,4525 v1(6455,4525) ; v1(6655,4735) 6655,4795.51 6849.49,4990 7114.49,4990 7230,5105.51 7230,5250.41 7341.59,5362 7632.89,5362 7708.71,5286.18 v1(7770,5286.18)
PB10: P3.11 U1.21 | length 2679.9
  Top Layer w10: U1.21 6602.71,4067.03 6650,4019.75 v1(6650,3985)
  Bottom Layer w10: v1(6650,3985) 6898.39,3985 7003.39,4090 7270,4090 7303,4057 7474.63,4057 8145,4727.37 8145,5070 8055,5160 7996.18,5160 v1(7870,5286.18)
PB11: R21.1 U1.22 | length 670.4
  Top Layer w10: R21.1 6330.8,3835.8 6375,3880 6655,3880 6685,3910 6685,4007.37 6622.4,4069.97 U1.22
PB12: R19.1 U1.25 | length 787.8
  Top Layer w10: R19.1 6430.8,3815.8 6477,3862 6712,3862 6837,3987 6837,4120.12 6790.79,4166.33 U1.25
PB13: R18.1 U1.26 | length 747.5
  Top Layer w10: R18.1 6530.8,3835.8 6541,3846 6718.63,3846 6853,3980.37 6853,4126.75 6793.73,4186.02 U1.26
PB14: R17.1 U1.27 | length 683.7
  Top Layer w10: R17.1 6630.8,3815.8 6645,3830 6725.25,3830 6869,3973.75 6869,4133.37 6796.67,4205.7 U1.27
PB15: R5.1 U1.28 | length 629.9
  Top Layer w10: U1.28 6799.61,4225.39 6885,4140 6885,3967.12 6730.8,3812.92 R5.1
PC13: P3.10 U1.2 | length 2384.4
  Top Layer w10: v1(6340,4395) 6340,4370 6346.82,4363.18 U1.2 ; v1(6380,4652.5) 6434.5,4707 6577,4707 v1(6605,4735)
  Bottom Layer w10: v1(6340,4395) 6340,4610 6380,4650 v1(6380,4652.5) v1@6380,4655 ; v1(6605,4735) 6605,4768.14 6843.43,5006.57 7108.43,5006.57 7214,5112.14 7214,5257.04 7334.96,5378 7814.53,5378 7906.35,5286.18 v1(7970,5286.18)
PC14: P3.9 U1.3 | length 2593
  Top Layer w10: v1(6290,4360) 6306.5,4343.5 U1.3 ; v1(6355,4675) 6403,4723 6548,4723 v1(6560,4735)
  Bottom Layer w10: v1(6290,4360) 6290,4610 v1(6355,4675) ; v1(6560,4735) 6560,4745.76 6836.8,5022.57 7101.8,5022.57 7198,5118.76 7198,5263.66 7328.34,5394 7906,5394 8010,5290 v1(8070,5290)
PC15: U1.4
RXD: D7.A U1.31 | length 1586.1
  Top Layer w10: D7.A v1(6310.27,5449.73) ; U1.31 6860.56,4284.44 v1(6865,4280)
  Bottom Layer w10: v1(6310.27,5449.73) 6310.27,4824.73 6855,4280 v1(6865,4280)
TXD: R20.1 U1.30 | length 1639.3
  Top Layer w10: R20.1 v1(6270.54,5450) ; U1.30 6825.24,4264.76 6850,4240 v1(6850,4245)
  Bottom Layer w10: v1(6270.54,5450) 6270.54,4824.46 v1(6850,4245)
USB_N: U4.6 USB1.2 | length 594
  Top Layer w15: U4.6 6438.73,5063 6451.23,5075.5 6464.36,5075.5 6498.31,5109.45 USB1.2
USB_P: U4.5 USB1.3 | length 552.4
  Top Layer w15: U4.5 6438.73,5113 6451.23,5100.5 6454,5100.5 6472.72,5119.22 USB1.3
VBAT: U1.1
VCC: C7.1 C8.2 C12.1 P1.1 P2.6 P5.1 R10.2 R11.2 U2.3 U3.3 U4.16 USB1.1 | length 4826.3
  Top Layer w10: U4.16@6618.31,5313 C7.1@6737,5313
  Top Layer w20: USB1.1 6523.9,5481.1 6600,5405 6710,5405 6750,5365 C7.1 ; v1(6907.54,4704) R11.2 6732,4773 6670,4835 6670,5213.27 C7.1 ; U2.3@6938.86,5338.46 C8.2 6859.8,5333.27 6790,5333.27 C7.1 ; v1(7117.43,4380.14) 7117.43,4312.43 7108.46,4303.46 C12.1 6953.46,4303.46 6935,4285 6935,3915 6945,3905 P2.6 6945,3575 6975,3545 7355,3545 7390,3580 7390,3670 7415,3695 8010,3695 8108.68,3793.68 P1.1 8072.5,3872.5 8010,3935 8010,4065 8067.5,4122.5 P5.1 P5.1@8157.5,4122.5
  Bottom Layer w20: v1(6907.54,4704) 6907.54,4632.46 7117.43,4422.57 v1(7117.43,4380.14)
X_N: C15.1 U4.7 X2.1 | length 570.5
  Top Layer w15: C15.1 6137.54,5022.54 6210,5095 X2.1 6210,5039.5 6249,5000.5 6354.14,5000.5 6366.64,5013 U4.7
X_P: C16.1 U4.8 X2.2 | length 478.6
  Top Layer w15: C16.1@6070,4921.46 6132.54,4921.46 6210,4844 6210,4936.5 6249,4975.5 6354.14,4975.5 6366.64,4963 U4.8
pads on no net: K1.0 P2.0 U3.5 U4.9 U4.10 U4.11 U4.12 U4.13 U4.14 U4.15 U5.2 U5.3 U5.4 U5.5 U5.6 U5.7 U5.14 U5.15 U5.16 U5.17 U5.19 U5.21 U5.22 U5.25 USB1.0
copper on no net:
  other v2: 7120.95,4607.45 7164.25,4607.45 7120.95,4650.75 7164.25,4650.75

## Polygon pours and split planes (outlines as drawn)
24V on Top Layer "Top Layer-No Net" (solid, remove dead copper, pour order 0): 6874.08,5770.67 6849.88,5707.34 6923.93,5500 7125,5500 7235,5390 8092.19,5390 8190,5297.94 8190,3821.23 8015.55,3655 8000,3655 7575,3655 7510,3590 7510,3520.15 7522.48,3495 7530,3487.48 7532.48,3485 8350,3480 8345,5770 8340,5775
GND on Top Layer "Top Layer-No Net" (solid, remove dead copper, pour order 4): 5900,5865 5940,5825 5940,3400 8360,3400 8390,3370 8480,3460 8480,5855
GND on Bottom Layer "Top Layer-No Net" (solid, remove dead copper, pour order 6): 5875,6010 5875,3070 5860,3055 5880,3075 8765,3075 8765,5630 8560,5835

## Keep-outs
Keep-Out Layer:
  circle w0.5: c8126.77,3649.96 r59.06
  circle w0.5: c6158.27,5613.37 r59.06
  circle w0.5: c8126.77,5613.37 r59.06
  circle w0.5: c6158.27,3649.96 r59.06
  lines w0.5: 6138.58,3487.38 cw(c6138.58,3625.18) 6000.79,3625.18 6000.79,5633.05 cw(c6138.58,5633.05) 6138.58,5770.85 8146.46,5770.85 cw(c8146.46,5633.05) 8284.25,5633.05 8284.25,3625.18 ; 6138.58,3487.48 8146.46,3487.48 ; 8146.46,3492.48 ccw(c8146.46,3630.28) 8284.25,3630.28

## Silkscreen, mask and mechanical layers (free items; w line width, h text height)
Top Overlay:
  lines w10: 7325,4865 7325,4985 8120,4985 8120,4850 7340,4850 7325,4865 ; 7325,5385 8120,5385 8120,5520 7340,5520 7325,5505 7325,5385
  text "24V" at 7255,5755 h50 r180
  text "USART" at 6630,5535 h50 r180
  text "PB1" at 7385,5400 h30 r90
  text "PB3" at 7485,5400 h30 r90
  text "PB4" at 7585,5400 h30 r90
  text "PB8" at 7685,5400 h30 r90
  text "PB9" at 7785,5400 h30 r90
  text "PB10" at 7885,5400 h30 r90
  text "PC13" at 7985,5400 h30 r90
  text "PC14" at 8085,5400 h30 r90
  text "PA0" at 7385,4865 h30 r90
  text "PA1" at 7485,4865 h30 r90
  text "PA4" at 7585,4865 h30 r90
  text "PA5" at 7685,4865 h30 r90
  text "PA6" at 7785,4865 h30 r90
  text "PA7" at 7885,4865 h30 r90
  text "PA8" at 7985,4865 h30 r90
  text "PB0" at 8085,4865 h30 r90
  text "SWC" at 7765,4215 h20
  text "GND" at 8200,4210 h20
  text "SWD" at 7765,4115 h20
  text "VCC" at 8200,4110 h20
  text "TX" at 7780,3965 h20
  text "GND" at 8200,3960 h20
  text "RX" at 7780,3865 h20
  text "VCC" at 8200,3860 h20
  text "VCC" at 6955,3835 h20 r90
  text "GND" at 7230,3835 h20 r90
  text "24V" at 7350,3835 h20 r90
  text "CANP" at 7035,3825 h20 r90
  text "CANN" at 7115,3825 h20 r90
